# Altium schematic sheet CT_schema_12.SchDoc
size 387 x 385 mm
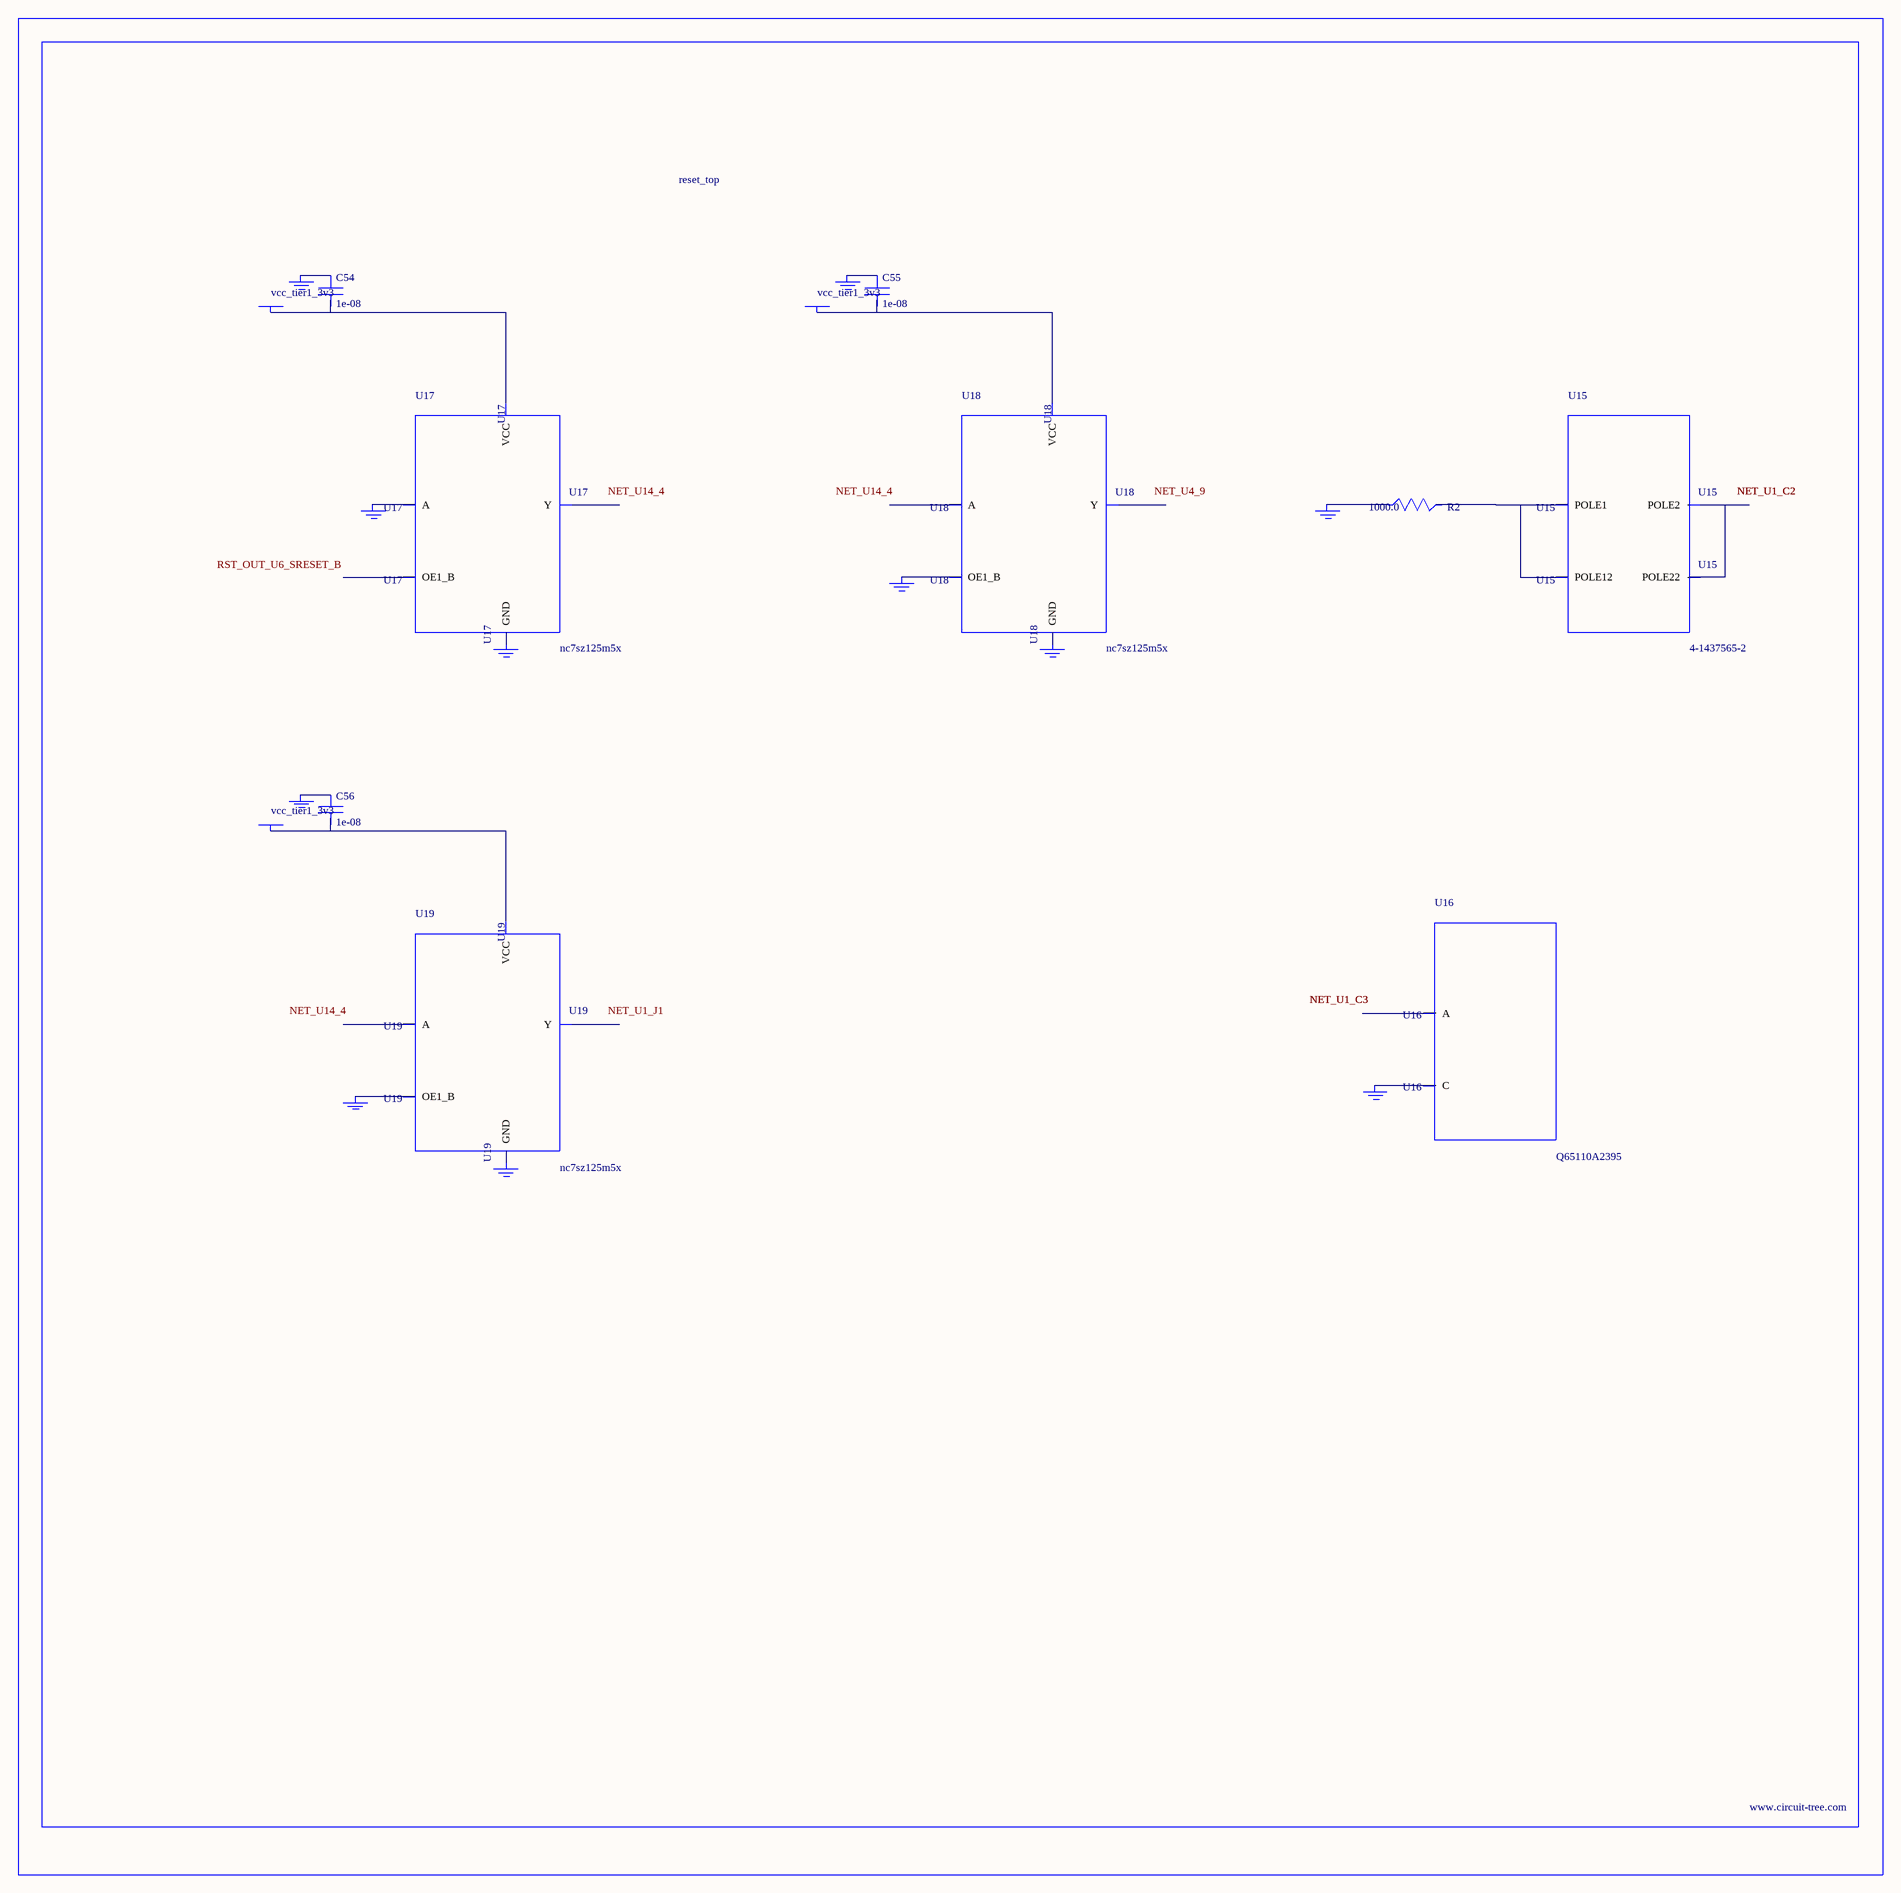
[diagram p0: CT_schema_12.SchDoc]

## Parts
BORDER11  (no value)
C54  1e-08  [C0402]
C55  1e-08  [C0402]
C56  1e-08  [C0402]
GND_INSTANCE_11_0  (no value)
GND_INSTANCE_11_1  (no value)
GND_INSTANCE_11_2  (no value)
GND_INSTANCE_11_3  (no value)
GND_INSTANCE_11_4  (no value)
GND_INSTANCE_11_5  (no value)
GND_INSTANCE_11_6  (no value)
GND_INSTANCE_11_7  (no value)
GND_INSTANCE_11_8  (no value)
GND_INSTANCE_11_9  (no value)
GND_INSTANCE_11_10  (no value)
POWER_INSTANCE_11_0  vcc_tier1_3v3
POWER_INSTANCE_11_1  vcc_tier1_3v3
POWER_INSTANCE_11_2  vcc_tier1_3v3
R2  1000.0  [R0603]
U15  4-1437565-2  [SW_4-1437565-2]
U16  Q65110A2395  [LGM67K-G1J2-24-Z]
U17  nc7sz125m5x  [NC7SZ125M5X]
U18  nc7sz125m5x  [NC7SZ125M5X]
U19  nc7sz125m5x  [NC7SZ125M5X]

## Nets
NetC54_1: C54.1 GND_INSTANCE_11_2.0(GND)
NetC54_2: C54.2 POWER_INSTANCE_11_0.0(PWR) U17.5(VCC)
NetC55_1: C55.1 GND_INSTANCE_11_5.0(GND)
NetC55_2: C55.2 POWER_INSTANCE_11_1.0(PWR) U18.5(VCC)
NetC56_1: C56.1 GND_INSTANCE_11_8.0(GND)
NetC56_2: C56.2 POWER_INSTANCE_11_2.0(PWR) U19.5(VCC)
NetGND_INSTANCE_11_0_0: GND_INSTANCE_11_0.0(GND) R2.1
NetGND_INSTANCE_11_1_0: GND_INSTANCE_11_1.0(GND) U16.C
NetGND_INSTANCE_11_3_0: GND_INSTANCE_11_3.0(GND) U17.2(A)
NetGND_INSTANCE_11_4_0: GND_INSTANCE_11_4.0(GND) U17.3(GND)
NetGND_INSTANCE_11_6_0: GND_INSTANCE_11_6.0(GND) U18.1(OE1_B)
NetGND_INSTANCE_11_7_0: GND_INSTANCE_11_7.0(GND) U18.3(GND)
NetGND_INSTANCE_11_9_0: GND_INSTANCE_11_9.0(GND) U19.1(OE1_B)
NetGND_INSTANCE_11_10_0: GND_INSTANCE_11_10.0(GND) U19.3(GND)
NetR2_2: R2.2 U15.1(POLE1) U15.2(POLE12)
NetU15_3: U15.3(POLE2) U15.4(POLE22)

Not connected (* = marked no-connect by the designer): U16 A; U17 1(OE1_B) 4(Y); U18 2(A) 4(Y); U19 2(A) 4(Y)

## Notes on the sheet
- Labels drawn without touching a wire or pin: NET_U1_J1, NET_U4_9, NET_U14_4, RST_OUT_U6_SRESET_B

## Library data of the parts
BORDER11 = BORDER_PAGE11
C54-C56 = C0402C103K3RAC
GND_INSTANCE_11_0-GND_INSTANCE_11_10 = GND
POWER_INSTANCE_11_0-POWER_INSTANCE_11_2 = PWR
R2 = RC0603JR-071KL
